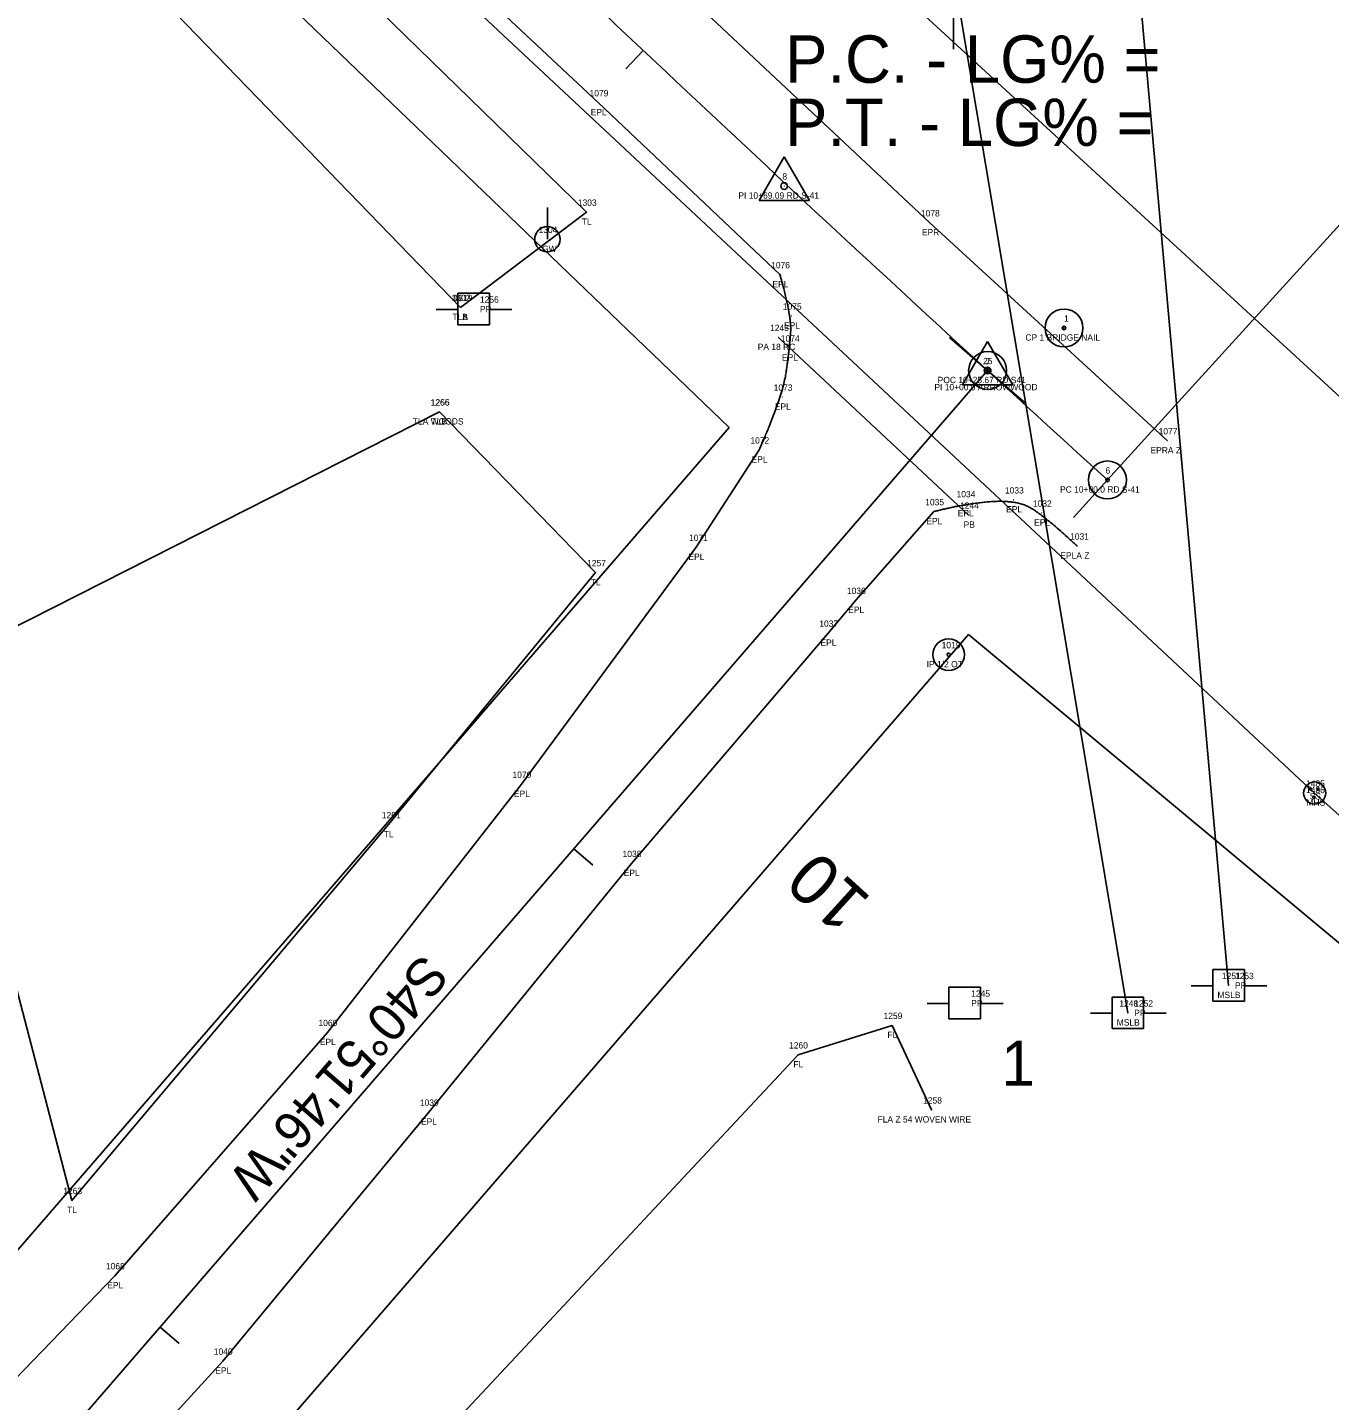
# Model space of a CAD drawing. Extents: x 1812113 to 1819860, y 1177395 to 1181185.
# Drawn here: x 1813896.2 to 1814102.1, y 1178275.6 to 1178492.8 of the extents above; entities that cross this region are included whole.
import ezdxf

# ---------------------------------------------------------------- set-up
doc = ezdxf.new("R2010")
doc.units = 0
for name, color, linetype in [('RD_EX_DR_Inlet', 7, 'Continuous'), ('RD_EX_DR_Pipe', 7, 'Continuous'), ('RD_EX_DR_Pipe_txCode', 7, 'Continuous'), ('RD_EX_DV_Prop', 7, 'Continuous'), ('RD_EX_DV_Prop_txCode', 7, 'Continuous'), ('RD_EX_DV_PropPin', 7, 'Continuous'), ('RD_EX_DV_TX_Prop', 7, 'Continuous'), ('RD_EX_Fence_Other', 7, 'Continuous'), ('RD_EX_Fence_Other_txCode', 7, 'Continuous'), ('RD_EX_Misc', 7, 'Continuous'), ('RD_EX_Misc_txCode', 7, 'Continuous'), ('RD_EX_Road', 7, 'Continuous'), ('RD_EX_Road_txCode', 7, 'Continuous'), ('RD_EX_UT', 7, 'Continuous'), ('RD_EX_UT_txCode', 7, 'Continuous'), ('RD_EX_VEG', 7, 'Continuous'), ('RD_EX_VEG_txCode', 7, 'Continuous'), ('RD_HC_CL', 7, 'Continuous'), ('RD_HC_Data', 7, 'Continuous'), ('RD_HC_Data_Tic', 7, 'Continuous'), ('RD_HC_TX_Sta50', 7, 'Continuous'), ('RD_HC_TX_StaOther', 7, 'Continuous'), ('RD_HC_txCode', 7, 'Continuous'), ('RD_SMD_Locator', 7, 'Continuous')]:
    doc.layers.add(name, color=color, linetype=linetype)

msp = doc.modelspace()

# ---------------------------------------------------------------- linework, layer by layer
at = {"layer": 'RD_EX_DR_Inlet'}
for centre, radius in [((1814099.72, 1178371.7), 1.75), ((1814099.05, 1178372.33), 0.175), ((1814100.28, 1178372.26), 0.175), ((1814099.63, 1178371.03), 0.175)]:
    msp.add_circle(centre, radius, dxfattribs=at)
at = {"layer": 'RD_EX_DR_Pipe'}
msp.add_line((1814014.96, 1178443.75), (1814045.01, 1178415.64), dxfattribs=at)
at = {"layer": 'RD_EX_DV_Prop'}
for p, q in [((1814007.16, 1178429.49), (1813828.61, 1178601.13)), ((1814146.51, 1178395.03), (1814011.17, 1178519.35)), ((1813876.31, 1178278.23), (1814007.16, 1178429.49)), ((1813914.12, 1178245.52), (1814044.97, 1178396.77)), ((1814044.97, 1178396.77), (1814207.9, 1178261.14))]:
    msp.add_line(p, q, dxfattribs=at)
at = {"layer": 'RD_EX_DV_PropPin'}
for radius in [2.5, 0.25]:
    msp.add_circle((1814041.85, 1178393.58), radius, dxfattribs=at)
at = {"layer": 'RD_EX_Fence_Other'}
msp.add_lwpolyline([(1814039.17, 1178321.6), (1814032.91, 1178334.96), (1814018.04, 1178330.3), (1813949.86, 1178257.34), (1813966.14, 1178241)], dxfattribs=at)
at = {"layer": 'RD_EX_Misc'}
for p, q in [((1814068.17, 1178541.96), (1814086.12, 1178341.27)), ((1814043.18, 1178498.23), (1814070.2, 1178336.93))]:
    msp.add_line(p, q, dxfattribs=at)
at = {"layer": 'RD_EX_Road'}
for p, q in [((1813986.47, 1178480.85), (1813949.15, 1178515.86)), ((1814015.19, 1178453.67), (1813986.47, 1178480.85)), ((1814001.91, 1178410.56), (1814011.9, 1178425.95)), ((1814039.53, 1178416.2), (1814027.18, 1178402.17)), ((1813974.31, 1178373.09), (1814001.91, 1178410.56)), ((1814027.18, 1178402.17), (1814022.8, 1178396.98)), ((1814022.8, 1178396.98), (1813991.69, 1178360.57)), ((1813943.63, 1178333.84), (1813974.31, 1178373.09)), ((1813991.69, 1178360.57), (1813959.64, 1178321.24)), ((1813910.02, 1178295.38), (1813943.63, 1178333.84)), ((1813959.64, 1178321.24), (1813927.09, 1178281.88)), ((1813874.69, 1178258.74), (1813910.02, 1178295.38)), ((1813927.09, 1178281.88), (1813899.48, 1178251.69))]:
    msp.add_line(p, q, dxfattribs=at)
msp.add_lwpolyline([(1814076.45, 1178427.4), (1814038.86, 1178461.87), (1814001.83, 1178496.62), (1813965.15, 1178531.54), (1813928.08, 1178567.1), (1813892.01, 1178601.23), (1813854.54, 1178636.51), (1813817.44, 1178670.03), (1813779.87, 1178701.64)], dxfattribs=at)
for points in [[(1814015.19, 1178453.67), (1814017.03, 1178447.13), (1814016.71, 1178442.08), (1814015.58, 1178434.3), (1814011.9, 1178425.95)], [(1814062.16, 1178410.76), (1814056.57, 1178415.98), (1814052.15, 1178418.06), (1814044.5, 1178417.46), (1814039.53, 1178416.2)]]:
    msp.add_open_spline(points, degree=2, dxfattribs=at)
at = {"layer": 'RD_EX_UT'}
for p, q in [((1813978.41, 1178459.26), (1813978.41, 1178464.26)), ((1813969.24, 1178450.74), (1813964.24, 1178450.74)), ((1813964.24, 1178450.74), (1813964.24, 1178445.74)), ((1813969.24, 1178445.74), (1813969.24, 1178450.74)), ((1813960.81, 1178448.18), (1813964.28, 1178448.18)), ((1813969.17, 1178448.18), (1813972.81, 1178448.18)), ((1813964.24, 1178445.74), (1813969.24, 1178445.74)), ((1814088.61, 1178343.78), (1814083.61, 1178343.78)), ((1814083.61, 1178343.78), (1814083.61, 1178338.78)), ((1814088.61, 1178338.78), (1814088.61, 1178343.78)), ((1814046.91, 1178340.99), (1814041.91, 1178340.99)), ((1814041.91, 1178340.99), (1814041.91, 1178335.99)), ((1814046.91, 1178335.99), (1814046.91, 1178340.99)), ((1814080.18, 1178341.22), (1814083.65, 1178341.22)), ((1814088.54, 1178341.22), (1814092.18, 1178341.22)), ((1814072.69, 1178339.44), (1814067.69, 1178339.44)), ((1814067.69, 1178339.44), (1814067.69, 1178334.44)), ((1814072.69, 1178334.44), (1814072.69, 1178339.44)), ((1814038.48, 1178338.43), (1814041.95, 1178338.43)), ((1814046.84, 1178338.43), (1814050.48, 1178338.43)), ((1814064.26, 1178336.88), (1814067.73, 1178336.88)), ((1814072.62, 1178336.88), (1814076.26, 1178336.88)), ((1814083.61, 1178338.78), (1814088.61, 1178338.78)), ((1814041.91, 1178335.99), (1814046.91, 1178335.99)), ((1814067.69, 1178334.44), (1814072.69, 1178334.44))]:
    msp.add_line(p, q, dxfattribs=at)
msp.add_lwpolyline([(1814122.48, 1178351.31), (1814099.73, 1178371.68), (1813807.05, 1178645.14), (1813817.45, 1178777.9), (1813883.81, 1178790.87)], dxfattribs=at)
msp.add_circle((1813978.41, 1178459.26), 2, dxfattribs=at)
at = {"layer": 'RD_EX_VEG'}
for points in [[(1813964.65, 1178448.48), (1813984.61, 1178463.55), (1813943.71, 1178503.46), (1813904.65, 1178537.57), (1813863.79, 1178578.71), (1813833.99, 1178603.93), (1813823.24, 1178594.53), (1813964.65, 1178448.48)], [(1813961.33, 1178431.97), (1813986.04, 1178406.55), (1813953.31, 1178366.71), (1813903.24, 1178307.28), (1813881.24, 1178391.37), (1813961.33, 1178431.97)]]:
    msp.add_lwpolyline(points, dxfattribs=at)
at = {"layer": 'RD_HC_CL'}
msp.add_line((1814048.02, 1178438.51), (1813851.74, 1178211.63), dxfattribs=at)
msp.add_arc((1817921.84, 1182660.75), 5730.08, 226.33932, 227.720866, dxfattribs=at)
at = {"layer": 'RD_HC_Data'}
for p, q in [((1814042.6, 1178489.32), (1814042.6, 1178507.65)), ((1814066.97, 1178421.2), (1814145.47, 1178507.54)), ((1814011.88, 1178465.39), (1814015.86, 1178472.27)), ((1814015.86, 1178472.27), (1814019.83, 1178465.39)), ((1814011.88, 1178465.39), (1814019.83, 1178465.39)), ((1814044.05, 1178436.22), (1814048.02, 1178443.1)), ((1814048.02, 1178443.1), (1814051.99, 1178436.22)), ((1814044.05, 1178436.22), (1814051.99, 1178436.22))]:
    msp.add_line(p, q, dxfattribs=at)
for centre, radius in [((1814015.86, 1178467.68), 0.529), ((1814060.1, 1178445.23), 3), ((1814060.1, 1178445.23), 0.282), ((1814048.02, 1178438.51), 3), ((1814048.02, 1178438.51), 0.529), ((1814048.02, 1178438.51), 0.282), ((1814066.97, 1178421.2), 3), ((1814066.97, 1178421.2), 0.282)]:
    msp.add_circle(centre, radius, dxfattribs=at)
at = {"layer": 'RD_HC_Data_Tic'}
for p, q in [((1813993.57, 1178489.12), (1813990.83, 1178486.21)), ((1814048.02, 1178438.51), (1814041.97, 1178443.74)), ((1814048.02, 1178438.51), (1814054.07, 1178433.28)), ((1814066.97, 1178421.2), (1814072.35, 1178427.12)), ((1814066.97, 1178421.2), (1814061.59, 1178415.28)), ((1813982.59, 1178362.88), (1813985.62, 1178360.27)), ((1813917.17, 1178287.25), (1813920.19, 1178284.64))]:
    msp.add_line(p, q, dxfattribs=at)
at = {"layer": 'RD_SMD_Locator'}
for centre in [(1813986.47, 1178480.85), (1814015.86, 1178467.68), (1813984.61, 1178463.55), (1814038.86, 1178461.87), (1814015.19, 1178453.67), (1813964.65, 1178448.48), (1813964.65, 1178448.48), (1814017.03, 1178447.13), (1814060.1, 1178445.23), (1814014.96, 1178443.75), (1814016.71, 1178442.08), (1814048.02, 1178438.51), (1814048.02, 1178438.51), (1814015.58, 1178434.3), (1813961.33, 1178431.97), (1813961.33, 1178431.97), (1814011.9, 1178425.95), (1814076.45, 1178427.4), (1814066.97, 1178421.2), (1814044.5, 1178417.46), (1814052.15, 1178418.06), (1814039.53, 1178416.2), (1814045.01, 1178415.64), (1814056.57, 1178415.98), (1814001.91, 1178410.56), (1814062.16, 1178410.76), (1813986.04, 1178406.55), (1814027.18, 1178402.17), (1814022.8, 1178396.98), (1813974.31, 1178373.09), (1814099.73, 1178371.68), (1813953.31, 1178366.71), (1813991.69, 1178360.57), (1814086.12, 1178341.27), (1814070.2, 1178336.93), (1814032.91, 1178334.96), (1813943.63, 1178333.84), (1814018.04, 1178330.3), (1814039.17, 1178321.6), (1813959.64, 1178321.24), (1813903.24, 1178307.28), (1813910.02, 1178295.38), (1813927.09, 1178281.88)]:
    msp.add_circle(centre, 0.001, dxfattribs=at)

# ---------------------------------------------------------------- texts
at = {"layer": 'RD_EX_DR_Pipe_txCode'}
for s, p in [('1243', (1814013.62, 1178444.75)), ('PA 18 RC', (1814011.67, 1178441.75)), ('1244', (1814043.66, 1178416.64)), ('PB', (1814044.23, 1178413.64))]:
    msp.add_text(s, height=1, dxfattribs=at).set_placement(p)
at = {"layer": 'RD_EX_DV_Prop_txCode'}
for s, p in [('1019', (1814040.75, 1178394.58)), ('IP 1/2 OT', (1814038.38, 1178391.58))]:
    msp.add_text(s, height=1, dxfattribs=at).set_placement(p)
at = {"layer": 'RD_EX_DV_TX_Prop'}
msp.add_text('1', height=7.14, dxfattribs=at).set_placement((1814050.18, 1178325.4))
at = {"layer": 'RD_EX_Fence_Other_txCode'}
for s, p in [('1259', (1814031.56, 1178335.96)), ('1260', (1814016.63, 1178331.3)), ('FL', (1814032.18, 1178332.96)), ('FL', (1814017.31, 1178328.3)), ('1258', (1814037.82, 1178322.6)), ('FLA Z 54 WOVEN WIRE', (1814030.62, 1178319.6))]:
    msp.add_text(s, height=1, dxfattribs=at).set_placement(p)
at = {"layer": 'RD_EX_Misc_txCode'}
for s, p in [('1251', (1814085.06, 1178342.27)), ('1248', (1814068.85, 1178337.93)), ('MSLB', (1814084.36, 1178339.27)), ('MSLB', (1814068.43, 1178334.93))]:
    msp.add_text(s, height=1, dxfattribs=at).set_placement(p)
at = {"layer": 'RD_EX_Road_txCode'}
for s, p in [('1079', (1813985.08, 1178481.85)), ('EPL', (1813985.26, 1178478.85)), ('1078', (1814037.47, 1178462.87)), ('EPR', (1814037.63, 1178459.87)), ('1076', (1814013.79, 1178454.67)), ('EPL', (1814013.99, 1178451.67)), ('1075', (1814015.64, 1178448.13)), ('EPL', (1814015.83, 1178445.13)), ('1074', (1814015.32, 1178443.08)), ('EPL', (1814015.5, 1178440.08)), ('1073', (1814014.19, 1178435.3)), ('EPL', (1814014.37, 1178432.3)), ('1072', (1814010.51, 1178426.95)), ('1077', (1814075.06, 1178428.4)), ('EPRA Z', (1814073.77, 1178425.4)), ('EPL', (1814010.69, 1178423.95)), ('1034', (1814043.11, 1178418.46)), ('1033', (1814050.76, 1178419.06)), ('1035', (1814038.15, 1178417.2)), ('EPL', (1814050.94, 1178416.06)), ('1032', (1814055.18, 1178416.98)), ('EPL', (1814038.33, 1178414.2)), ('EPL', (1814043.29, 1178415.46)), ('EPL', (1814055.37, 1178413.98)), ('1031', (1814061.06, 1178411.76)), ('1071', (1814000.81, 1178411.56)), ('EPL', (1814000.71, 1178408.56)), ('EPLA Z', (1814059.51, 1178408.76)), ('1036', (1814025.77, 1178403.17)), ('EPL', (1814025.97, 1178400.17)), ('1037', (1814021.41, 1178397.98)), ('EPL', (1814021.59, 1178394.98)), ('1070', (1813972.89, 1178374.09)), ('EPL', (1813973.11, 1178371.09)), ('1038', (1813990.3, 1178361.57)), ('EPL', (1813990.48, 1178358.57)), ('1069', (1813942.22, 1178334.84)), ('EPL', (1813942.43, 1178331.84)), ('1039', (1813958.25, 1178322.24)), ('EPL', (1813958.43, 1178319.24)), ('1068', (1813908.61, 1178296.38)), ('EPL', (1813908.82, 1178293.38)), ('1040', (1813925.67, 1178282.88)), ('EPL', (1813925.89, 1178279.88))]:
    msp.add_text(s, height=1, dxfattribs=at).set_placement(p)
at = {"layer": 'RD_EX_UT_txCode'}
for s, p in [('1304', (1813977.02, 1178460.26)), ('GW', (1813977.57, 1178457.26)), ('1256', (1813967.75, 1178449.23)), ('PP', (1813967.75, 1178447.73)), ('1485', (1814098.37, 1178372.7)), ('1486', (1814098.36, 1178371.68)), ('SS', (1814098.95, 1178370.68)), ('MHS', (1814098.42, 1178369.7)), ('1253', (1814087.12, 1178342.27)), ('PP', (1814087.12, 1178340.77)), ('1245', (1814045.42, 1178339.48)), ('PP', (1814045.42, 1178337.98)), ('1252', (1814071.2, 1178337.93)), ('PP', (1814071.2, 1178336.43))]:
    msp.add_text(s, height=1, dxfattribs=at).set_placement(p)
at = {"layer": 'RD_EX_VEG_txCode'}
for s, p in [('1303', (1813983.22, 1178464.55)), ('TL', (1813983.84, 1178461.55)), ('1302', (1813963.27, 1178449.48)), ('1319', (1813963.59, 1178449.48)), ('TLA', (1813963.39, 1178446.48)), ('TLB', (1813963.41, 1178446.48)), ('1266', (1813959.94, 1178432.97)), ('1255', (1813959.99, 1178432.97)), ('TLA WOODS', (1813957.13, 1178429.97)), ('TLB', (1813960.09, 1178429.97)), ('1257', (1813984.69, 1178407.55)), ('TL', (1813985.27, 1178404.55)), ('1261', (1813952.23, 1178367.71)), ('TL', (1813952.54, 1178364.71)), ('1263', (1813901.87, 1178308.28)), ('TL', (1813902.47, 1178305.28))]:
    msp.add_text(s, height=1, dxfattribs=at).set_placement(p)
at = {"layer": 'RD_HC_Data'}
msp.add_text('S40%%d51\'46"W', height=6, rotation=229.1372, dxfattribs=at).set_placement((1813958.67, 1178346.55))
at = {"layer": 'RD_HC_TX_Sta50'}
msp.add_text('10', height=8, rotation=137.7209, dxfattribs=at).set_placement((1814029.86, 1178354.93))
at = {"layer": 'RD_HC_TX_StaOther'}
for s, p in [('P.C. - LG% = ', (1814016, 1178484)), ('P.T. - LG% = ', (1814016, 1178474))]:
    msp.add_text(s, height=7.5, dxfattribs=at).set_placement(p)
at = {"layer": 'RD_HC_txCode'}
for s, p in [('8', (1814015.57, 1178468.68)), ('PI 10+69.09 RD S-41', (1814008.61, 1178465.68)), ('1', (1814060.1, 1178446.23)), ('CP 1 BRIDGE NAIL', (1814053.99, 1178443.23)), ('25', (1814047.29, 1178439.51)), ('7', (1814047.74, 1178439.51)), ('POC 10+25.67 RD S41', (1814040.12, 1178436.51)), ('PI 10+00.0 ARROWWOOD', (1814039.6, 1178435.38)), ('6', (1814066.66, 1178422.2)), ('PC 10+00.0 RD S-41', (1814059.47, 1178419.2))]:
    msp.add_text(s, height=1, dxfattribs=at).set_placement(p)

doc.saveas('drawing.dxf')
